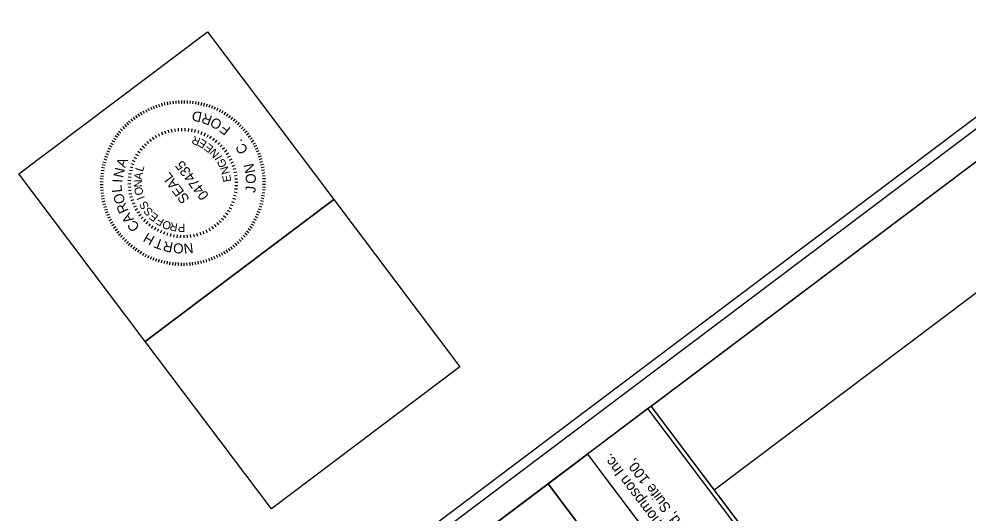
# Model space of a CAD drawing. Extents: x 1262337 to 1264328, y 775525 to 777528.
# Drawn here: x 1262336.8 to 1262789.6, y 776945.7 to 777181.3 of the extents above; entities that cross this region are included whole.
import ezdxf

# ---------------------------------------------------------------- set-up
doc = ezdxf.new("R2010")
doc.units = 0
for name, color, linetype in [('Default', 7, 'Continuous'), ('Raster_Level_0', 7, 'Continuous'), ('Sheet Data Field CELL', 7, 'Continuous'), ('Sheet Layout Plan Border', 7, 'Continuous'), ('Sheet Plan CELL', 7, 'Continuous'), ('Sheet Plan Layout CELL', 7, 'Continuous'), ('Sheet Plot Border Inside CELL', 7, 'Continuous'), ('Sheet Plot Border Outside CELL', 7, 'Continuous')]:
    doc.layers.add(name, color=color, linetype=linetype)

msp = doc.modelspace()

# ---------------------------------------------------------------- linework, layer by layer
at = {"layer": 'Default'}
for p, q in [((1262588.98, 776959.59), (1262607.75, 776973.72)), ((1262607.74, 776973.71), (1262728.05, 776813.98)), ((1262709.29, 776799.84), (1262588.97, 776959.58))]:
    msp.add_line(p, q, dxfattribs=at)
at = {"layer": 'Raster_Level_0'}
for points in [[(1262396.96, 777027.57), (1262336.81, 777107.43), (1262426.65, 777175.09), (1262486.79, 777095.24)], [(1262457.13, 776947.68), (1262396.96, 777027.57), (1262486.79, 777095.24), (1262546.97, 777015.35)], [(1262559.28, 776812.07), (1262499.13, 776891.92), (1262588.97, 776959.59), (1262649.11, 776879.74)]]:
    msp.add_lwpolyline(points, close=True, dxfattribs=at)
at = {"layer": 'Sheet Data Field CELL'}
for p, q in [((1262399.51, 777139.33), (1262400.05, 777138.06)), ((1262400.78, 777139.87), (1262401.28, 777138.57)), ((1262402.08, 777140.31), (1262402.51, 777139.01)), ((1262403.37, 777140.73), (1262403.76, 777139.42)), ((1262404.69, 777141.13), (1262405.05, 777139.78)), ((1262406.04, 777141.42), (1262406.35, 777140.11)), ((1262407.37, 777141.71), (1262407.66, 777140.37)), ((1262408.74, 777141.97), (1262408.93, 777140.61)), ((1262410.1, 777142.15), (1262410.29, 777140.8)), ((1262411.49, 777142.3), (1262411.58, 777140.92)), ((1262412.84, 777142.42), (1262412.92, 777141.03)), ((1262414.21, 777142.43), (1262414.22, 777141.06)), ((1262415.58, 777142.43), (1262415.55, 777141.04)), ((1262416.98, 777142.41), (1262416.89, 777141.02)), ((1262418.33, 777142.29), (1262418.21, 777140.94)), ((1262419.68, 777142.17), (1262419.52, 777140.79)), ((1262421.05, 777141.94), (1262420.86, 777140.6)), ((1262422.42, 777141.71), (1262422.17, 777140.38)), ((1262423.76, 777141.45), (1262423.46, 777140.09)), ((1262425.11, 777141.09), (1262424.75, 777139.75)), ((1262426.43, 777140.71), (1262426.04, 777139.39)), ((1262427.73, 777140.32), (1262427.28, 777139.01)), ((1262429, 777139.83), (1262428.54, 777138.53)), ((1262430.29, 777139.3), (1262429.74, 777138.06)), ((1262392.28, 777135.32), (1262393.08, 777134.18)), ((1262393.44, 777136.08), (1262394.17, 777134.94)), ((1262394.61, 777136.84), (1262395.33, 777135.65)), ((1262395.79, 777137.49), (1262396.45, 777136.31)), ((1262397.02, 777138.18), (1262397.66, 777136.92)), ((1262398.24, 777138.79), (1262398.84, 777137.51)), ((1262431.56, 777138.75), (1262430.96, 777137.47)), ((1262432.77, 777138.17), (1262432.15, 777136.92)), ((1262434, 777137.48), (1262433.33, 777136.31)), ((1262435.18, 777136.81), (1262434.5, 777135.64)), ((1262436.38, 777136.08), (1262435.6, 777134.9)), ((1262437.5, 777135.32), (1262436.69, 777134.16)), ((1262387.04, 777130.89), (1262387.99, 777129.93)), ((1262388.03, 777131.88), (1262388.97, 777130.86)), ((1262389.04, 777132.76), (1262389.93, 777131.75)), ((1262390.09, 777133.67), (1262390.97, 777132.59)), ((1262391.2, 777134.51), (1262392.04, 777133.4)), ((1262438.59, 777134.52), (1262437.79, 777133.43)), ((1262439.7, 777133.67), (1262438.83, 777132.6)), ((1262440.73, 777132.78), (1262439.83, 777131.74)), ((1262441.78, 777131.88), (1262440.81, 777130.85)), ((1262442.76, 777130.87), (1262441.8, 777129.93)), ((1262382.63, 777125.66), (1262383.76, 777124.88)), ((1262383.4, 777126.79), (1262384.52, 777125.95)), ((1262384.28, 777127.86), (1262385.35, 777126.99)), ((1262385.14, 777128.93), (1262386.21, 777127.99)), ((1262386.07, 777129.94), (1262387.11, 777128.97)), ((1262402.57, 777124.6), (1262401.88, 777125.76)), ((1262403.96, 777125.29), (1262403.32, 777126.55)), ((1262405.39, 777125.95), (1262404.82, 777127.25)), ((1262406.84, 777126.49), (1262406.37, 777127.83)), ((1262408.3, 777126.95), (1262407.94, 777128.29)), ((1262409.82, 777127.3), (1262409.55, 777128.72)), ((1262411.34, 777127.61), (1262411.15, 777128.97)), ((1262412.9, 777127.77), (1262412.79, 777129.19)), ((1262414.45, 777127.86), (1262414.44, 777129.22)), ((1262416.02, 777127.84), (1262416.07, 777129.2)), ((1262417.58, 777127.69), (1262417.74, 777129.07)), ((1262419.12, 777127.47), (1262419.35, 777128.84)), ((1262420.66, 777127.19), (1262420.98, 777128.51)), ((1262422.17, 777126.77), (1262422.57, 777128.08)), ((1262423.63, 777126.26), (1262424.09, 777127.56)), ((1262425.05, 777125.64), (1262425.65, 777126.93)), ((1262426.46, 777124.96), (1262427.12, 777126.24)), ((1262443.72, 777129.93), (1262442.7, 777128.98)), ((1262444.63, 777128.87), (1262443.59, 777127.96)), ((1262445.51, 777127.86), (1262444.43, 777126.99)), ((1262446.35, 777126.75), (1262445.24, 777125.91)), ((1262380.43, 777122.13), (1262381.64, 777121.49)), ((1262381.11, 777123.38), (1262382.31, 777122.66)), ((1262381.83, 777124.51), (1262382.98, 777123.76)), ((1262397.59, 777120.85), (1262396.63, 777121.81)), ((1262398.73, 777121.89), (1262397.82, 777122.94)), ((1262399.96, 777122.88), (1262399.13, 777123.98)), ((1262401.21, 777123.76), (1262400.46, 777124.92)), ((1262427.8, 777124.24), (1262428.54, 777125.39)), ((1262429.11, 777123.36), (1262429.93, 777124.52)), ((1262430.35, 777122.44), (1262431.22, 777123.5)), ((1262431.54, 777121.41), (1262432.51, 777122.44)), ((1262432.65, 777120.33), (1262433.68, 777121.29)), ((1262447.19, 777125.64), (1262446.05, 777124.84)), ((1262447.92, 777124.51), (1262446.75, 777123.76)), ((1262448.68, 777123.34), (1262447.49, 777122.62)), ((1262449.35, 777122.12), (1262448.18, 777121.46)), ((1262378.12, 777117.16), (1262379.38, 777116.67)), ((1262378.61, 777118.42), (1262379.89, 777117.9)), ((1262379.2, 777119.72), (1262380.41, 777119.13)), ((1262379.78, 777120.93), (1262381.03, 777120.31)), ((1262393.72, 777115.96), (1262392.53, 777116.67)), ((1262394.59, 777117.27), (1262393.43, 777118.09)), ((1262395.51, 777118.51), (1262394.42, 777119.42)), ((1262396.55, 777119.7), (1262395.47, 777120.64)), ((1262433.72, 777119.15), (1262434.77, 777120.06)), ((1262434.72, 777117.99), (1262435.82, 777118.82)), ((1262435.59, 777116.67), (1262436.72, 777117.46)), ((1262450.02, 777120.93), (1262448.76, 777120.29)), ((1262450.6, 777119.68), (1262449.35, 777119.11)), ((1262451.17, 777118.44), (1262449.9, 777117.9)), ((1262451.68, 777117.14), (1262450.41, 777116.67)), ((1262376.82, 777113.24), (1262378.17, 777112.88)), ((1262377.21, 777114.56), (1262378.52, 777114.17)), ((1262377.63, 777115.89), (1262378.94, 777115.44)), ((1262391.66, 777111.77), (1262390.36, 777112.29)), ((1262392.24, 777113.22), (1262390.98, 777113.78)), ((1262392.95, 777114.59), (1262391.71, 777115.28)), ((1262436.4, 777115.35), (1262437.63, 777116.04)), ((1262437.13, 777113.99), (1262438.42, 777114.59)), ((1262437.79, 777112.56), (1262439.05, 777113.1)), ((1262452.15, 777115.87), (1262450.81, 777115.41)), ((1262452.57, 777114.58), (1262451.22, 777114.16)), ((1262452.93, 777113.23), (1262451.62, 777112.9)), ((1262375.78, 777107.84), (1262377.16, 777107.68)), ((1262375.94, 777109.22), (1262377.35, 777109.02)), ((1262376.2, 777110.55), (1262377.57, 777110.33)), ((1262376.5, 777111.92), (1262377.86, 777111.62)), ((1262390.76, 777108.82), (1262389.4, 777109.11)), ((1262391.14, 777110.3), (1262389.84, 777110.69)), ((1262438.33, 777111.12), (1262439.67, 777111.58)), ((1262438.81, 777109.61), (1262440.13, 777110.01)), ((1262439.17, 777108.09), (1262440.56, 777108.4)), ((1262453.29, 777111.88), (1262451.95, 777111.6)), ((1262453.58, 777110.55), (1262452.21, 777110.29)), ((1262453.81, 777109.21), (1262452.44, 777108.96)), ((1262453.99, 777107.85), (1262452.64, 777107.67)), ((1262375.52, 777103.74), (1262376.87, 777103.68)), ((1262375.54, 777105.14), (1262376.93, 777105.05)), ((1262375.63, 777106.46), (1262377.01, 777106.37)), ((1262390.11, 777104.18), (1262388.72, 777104.21)), ((1262390.22, 777105.71), (1262388.84, 777105.87)), ((1262390.44, 777107.25), (1262389.07, 777107.48)), ((1262439.44, 777106.54), (1262440.81, 777106.8)), ((1262439.64, 777105.01), (1262440.99, 777105.13)), ((1262439.7, 777103.5), (1262441.07, 777103.52)), ((1262454.14, 777106.46), (1262452.79, 777106.34)), ((1262454.26, 777105.11), (1262452.87, 777105.03)), ((1262454.3, 777103.71), (1262452.93, 777103.69)), ((1262375.49, 777102.33), (1262376.89, 777102.38)), ((1262375.53, 777101), (1262376.92, 777101.08)), ((1262375.61, 777099.62), (1262377.03, 777099.74)), ((1262390.1, 777102.61), (1262388.7, 777102.57)), ((1262390.18, 777101.06), (1262388.76, 777100.95)), ((1262390.34, 777099.5), (1262388.98, 777099.31)), ((1262439.34, 777098.79), (1262440.71, 777098.56)), ((1262439.56, 777100.34), (1262440.91, 777100.22)), ((1262439.68, 777101.93), (1262441.07, 777101.84)), ((1262454.16, 777099.58), (1262452.78, 777099.74)), ((1262454.25, 777100.97), (1262452.86, 777101.06)), ((1262454.3, 777102.33), (1262452.91, 777102.36)), ((1262375.77, 777098.23), (1262377.15, 777098.45)), ((1262375.95, 777096.87), (1262377.34, 777097.09)), ((1262376.17, 777095.54), (1262377.58, 777095.82)), ((1262376.49, 777094.17), (1262377.84, 777094.51)), ((1262390.61, 777097.95), (1262389.23, 777097.71)), ((1262390.94, 777096.47), (1262389.63, 777096.08)), ((1262391.42, 777094.97), (1262390.12, 777094.53)), ((1262438.1, 777094.32), (1262439.43, 777093.82)), ((1262438.61, 777095.78), (1262439.92, 777095.39)), ((1262439.03, 777097.29), (1262440.35, 777096.97)), ((1262453.29, 777094.2), (1262451.93, 777094.49)), ((1262453.55, 777095.53), (1262452.22, 777095.78)), ((1262453.81, 777096.86), (1262452.44, 777097.09)), ((1262454, 777098.2), (1262452.63, 777098.43)), ((1262376.82, 777092.85), (1262378.17, 777093.21)), ((1262377.22, 777091.53), (1262378.53, 777091.92)), ((1262377.61, 777090.21), (1262378.94, 777090.67)), ((1262378.08, 777088.94), (1262379.38, 777089.44)), ((1262391.96, 777093.52), (1262390.7, 777092.98)), ((1262392.62, 777092.09), (1262391.4, 777091.48)), ((1262393.35, 777090.73), (1262392.15, 777090.01)), ((1262436.04, 777090.12), (1262437.23, 777089.41)), ((1262436.83, 777091.45), (1262438.08, 777090.83)), ((1262437.51, 777092.86), (1262438.77, 777092.3)), ((1262452.16, 777090.22), (1262450.85, 777090.67)), ((1262452.58, 777091.49), (1262451.23, 777091.91)), ((1262452.94, 777092.83), (1262451.59, 777093.2)), ((1262378.62, 777087.67), (1262379.89, 777088.21)), ((1262379.16, 777086.4), (1262380.44, 777087)), ((1262379.77, 777085.18), (1262380.99, 777085.79)), ((1262394.19, 777089.37), (1262393.03, 777088.62)), ((1262395.07, 777088.12), (1262393.97, 777087.29)), ((1262396.06, 777086.89), (1262394.98, 777086.02)), ((1262397.1, 777085.75), (1262396.1, 777084.76)), ((1262432.2, 777085.26), (1262433.16, 777084.23)), ((1262433.27, 777086.37), (1262434.28, 777085.44)), ((1262434.31, 777087.56), (1262435.37, 777086.69)), ((1262435.2, 777088.84), (1262436.36, 777088.03)), ((1262449.97, 777085.15), (1262448.76, 777085.8)), ((1262450.59, 777086.39), (1262449.34, 777086.95)), ((1262451.14, 777087.66), (1262449.9, 777088.21)), ((1262451.7, 777088.91), (1262450.37, 777089.41)), ((1262380.43, 777083.92), (1262381.64, 777084.61)), ((1262381.11, 777082.77), (1262382.3, 777083.49)), ((1262381.84, 777081.57), (1262383.01, 777082.33)), ((1262382.6, 777080.48), (1262383.74, 777081.28)), ((1262398.21, 777084.68), (1262397.31, 777083.63)), ((1262399.4, 777083.64), (1262398.53, 777082.58)), ((1262400.64, 777082.72), (1262399.87, 777081.59)), ((1262401.95, 777081.85), (1262401.21, 777080.7)), ((1262403.32, 777081.08), (1262402.67, 777079.87)), ((1262404.73, 777080.4), (1262404.14, 777079.18)), ((1262425.86, 777080.78), (1262426.43, 777079.53)), ((1262427.22, 777081.51), (1262427.91, 777080.28)), ((1262428.54, 777082.32), (1262429.29, 777081.16)), ((1262429.83, 777083.23), (1262430.66, 777082.13)), ((1262431.02, 777084.19), (1262431.93, 777083.14)), ((1262447.16, 777080.45), (1262446.03, 777081.23)), ((1262447.92, 777081.57), (1262446.77, 777082.32)), ((1262448.68, 777082.73), (1262447.48, 777083.46)), ((1262449.35, 777083.91), (1262448.15, 777084.62)), ((1262383.4, 777079.33), (1262384.51, 777080.17)), ((1262384.28, 777078.25), (1262385.36, 777079.13)), ((1262385.12, 777077.21), (1262386.17, 777078.13)), ((1262386.07, 777076.19), (1262387.09, 777077.13)), ((1262387.02, 777075.17), (1262388.02, 777076.15)), ((1262406.19, 777079.81), (1262405.66, 777078.52)), ((1262407.62, 777079.34), (1262407.2, 777078.01)), ((1262409.13, 777078.92), (1262408.81, 777077.54)), ((1262410.66, 777078.57), (1262410.4, 777077.24)), ((1262412.21, 777078.35), (1262412.05, 777076.97)), ((1262413.77, 777078.27), (1262413.68, 777076.88)), ((1262415.31, 777078.23), (1262415.32, 777076.86)), ((1262416.86, 777078.32), (1262417, 777076.92)), ((1262418.41, 777078.47), (1262418.6, 777077.11)), ((1262419.96, 777078.74), (1262420.24, 777077.39)), ((1262421.45, 777079.14), (1262421.81, 777077.8)), ((1262422.96, 777079.62), (1262423.42, 777078.28)), ((1262424.43, 777080.12), (1262424.97, 777078.86)), ((1262442.74, 777075.15), (1262441.77, 777076.15)), ((1262443.72, 777076.18), (1262442.71, 777077.1)), ((1262444.65, 777077.18), (1262443.58, 777078.12)), ((1262445.51, 777078.25), (1262444.44, 777079.12)), ((1262446.39, 777079.32), (1262445.27, 777080.17)), ((1262388.02, 777074.23), (1262388.94, 777075.24)), ((1262389.02, 777073.3), (1262389.96, 777074.37)), ((1262390.09, 777072.44), (1262390.96, 777073.51)), ((1262391.16, 777071.56), (1262392.01, 777072.68)), ((1262392.25, 777070.76), (1262393.07, 777071.92)), ((1262437.48, 777070.76), (1262436.68, 777071.9)), ((1262438.62, 777071.56), (1262437.78, 777072.67)), ((1262439.66, 777072.41), (1262438.79, 777073.49)), ((1262440.74, 777073.28), (1262439.83, 777074.32)), ((1262441.77, 777074.23), (1262440.82, 777075.25)), ((1262393.41, 777070.03), (1262394.16, 777071.18)), ((1262394.57, 777069.27), (1262395.3, 777070.47)), ((1262395.78, 777068.56), (1262396.46, 777069.8)), ((1262396.98, 777067.91), (1262397.64, 777069.19)), ((1262398.19, 777067.33), (1262398.82, 777068.57)), ((1262399.46, 777066.78), (1262400.05, 777068.05)), ((1262400.75, 777066.25), (1262401.28, 777067.54)), ((1262402.06, 777065.79), (1262402.51, 777067.1)), ((1262427.71, 777065.8), (1262427.28, 777067.1)), ((1262429.01, 777066.24), (1262428.51, 777067.54)), ((1262430.28, 777066.78), (1262429.74, 777068.05)), ((1262431.55, 777067.32), (1262430.95, 777068.6)), ((1262432.77, 777067.93), (1262432.16, 777069.15)), ((1262433.99, 777068.56), (1262433.3, 777069.77)), ((1262435.18, 777069.27), (1262434.46, 777070.46)), ((1262436.34, 777069.97), (1262435.59, 777071.13)), ((1262403.35, 777065.34), (1262403.78, 777066.68)), ((1262404.71, 777064.98), (1262405.03, 777066.3)), ((1262406.04, 777064.66), (1262406.33, 777066.02)), ((1262407.36, 777064.33), (1262407.62, 777065.73)), ((1262408.73, 777064.1), (1262408.93, 777065.51)), ((1262410.07, 777063.92), (1262410.27, 777065.32)), ((1262411.42, 777063.79), (1262411.58, 777065.17)), ((1262412.81, 777063.7), (1262412.9, 777065.09)), ((1262414.18, 777063.64), (1262414.2, 777065.04)), ((1262415.58, 777063.62), (1262415.53, 777065.03)), ((1262416.95, 777063.69), (1262416.87, 777065.08)), ((1262418.33, 777063.77), (1262418.18, 777065.16)), ((1262419.65, 777063.94), (1262419.51, 777065.31)), ((1262421.05, 777064.14), (1262420.83, 777065.48)), ((1262422.39, 777064.37), (1262422.13, 777065.74)), ((1262423.75, 777064.62), (1262423.44, 777066)), ((1262425.1, 777064.98), (1262424.74, 777066.33)), ((1262426.38, 777065.35), (1262425.99, 777066.66))]:
    msp.add_line(p, q, dxfattribs=at)
msp.add_lwpolyline([(1262756.89, 776835.69), (1262636.54, 776995.47), (1262607.71, 776973.75), (1262728.05, 776813.98)], close=True, dxfattribs=at)
at = {"layer": 'Sheet Layout Plan Border'}
msp.add_lwpolyline([(1264180.22, 776342.84), (1263337.92, 777461.13), (1262668.14, 776956.65), (1262782.01, 776805.47), (1262613.08, 776678.23), (1263341.52, 775711.12)], close=True, dxfattribs=at)
at = {"layer": 'Sheet Plan CELL'}
msp.add_lwpolyline([(1262469.12, 776869.36), (1263371.6, 775671.18), (1264210.31, 776302.91), (1263307.84, 777501.07)], close=True, dxfattribs=at)
at = {"layer": 'Sheet Plan Layout CELL'}
for points in [[(1263371.64, 775671.18), (1264210.31, 776302.91), (1263307.85, 777501.06), (1262638.07, 776996.57), (1262782.01, 776805.47), (1262613.08, 776678.23)], [(1262782.01, 776805.47), (1262638.06, 776996.59), (1262469.11, 776869.37), (1262613.08, 776678.23)]]:
    msp.add_lwpolyline(points, close=True, dxfattribs=at)
at = {"layer": 'Sheet Plot Border Inside CELL'}
msp.add_lwpolyline([(1264304.66, 776181.82), (1263302.32, 777512.55), (1262459.63, 776877.83), (1263461.96, 775547.09)], close=True, dxfattribs=at)
at = {"layer": 'Sheet Plot Border Outside CELL'}
msp.add_lwpolyline([(1264328.45, 776183.46), (1263315.59, 777528.19), (1262440.94, 776869.39), (1263453.8, 775524.67)], close=True, dxfattribs=at)

# ---------------------------------------------------------------- texts
at = {"layer": 'Sheet Data Field CELL'}
for s, height, rotation, p in [('D', 4.79, 167.4842, (1262424.36, 777136.64)), ('R', 4.79, 158.8526, (1262429.29, 777134.84)), ('O', 4.79, 149.9332, (1262434.05, 777132.23)), ('F', 4.79, 141.7332, (1262438.01, 777129.2)), ('R', 3.88, 156.6864, (1262423.62, 777124.2)), ('E', 3.88, 148.3844, (1262426.68, 777122.54)), ('E', 3.88, 140.0823, (1262429.82, 777120.05)), ('C', 4.79, 119.5067, (1262446.18, 777118.51)), ('.', 4.79, 128.1383, (1262443.51, 777123.03)), ('N', 3.88, 131.7803, (1262432.58, 777117.09)), ('A', 4.79, 68.9785, (1262387.35, 777110.08)), ('047435', 4.791, 126.9874, (1262427.55, 777097.19)), ('I', 3.88, 123.4782, (1262433.84, 777115.58)), ('G', 3.88, 115.1762, (1262436.07, 777111.5)), ('N', 4.79, 101.7398, (1262449.41, 777108.22)), ('N', 4.79, 78.0086, (1262386.4, 777105.29)), ('A', 3.88, 82.4627, (1262395.42, 777104.46)), ('L', 3.88, 72.7539, (1262395.81, 777108.23)), ('SEAL', 4.791, 126.9874, (1262418.34, 777095.5)), ('N', 3.88, 106.8742, (1262437.33, 777107.84)), ('I', 4.79, 87.0386, (1262385.96, 777103.15)), ('N', 3.88, 92.1716, (1262395.52, 777101.06)), ('E', 3.88, 98.5721, (1262437.96, 777103.81)), ('O', 4.79, 92.8205, (1262449.79, 777102.81)), ('L', 4.79, 96.0686, (1262385.99, 777098.74)), ('O', 3.88, 101.8804, (1262396.2, 777097.61)), ('J', 4.79, 85.3397, (1262449.46, 777098.27)), ('O', 4.79, 105.0986, (1262387.52, 777093.77)), ('I', 3.88, 111.5892, (1262396.82, 777095.92)), ('S', 3.88, 121.298, (1262398.96, 777091.89)), ('R', 4.79, 114.1287, (1262389.2, 777089.88)), ('S', 3.88, 131.0069, (1262401.03, 777089.38)), ('A', 4.79, 123.1587, (1262391.76, 777085.75)), ('C', 4.79, 132.1887, (1262394.65, 777082.4)), ('E', 3.88, 140.7157, (1262403.54, 777087.24)), ('F', 3.88, 150.4245, (1262406.35, 777085.58)), ('O', 3.88, 160.1334, (1262409.76, 777084.07)), ('R', 3.88, 169.8422, (1262412.69, 777083.69)), ('P', 3.88, 179.551, (1262415.99, 777083.6)), ('H', 4.79, 150.2488, (1262401.92, 777077.27)), ('T', 4.79, 159.2788, (1262406.1, 777075.56)), ('R', 4.79, 168.3088, (1262410.54, 777074.52)), ('O', 4.79, 177.3388, (1262415.37, 777074.15)), ('N', 4.79, 186.3689, (1262419.61, 777074.58)), ('Johnson, Mirmiran, & Thompson Inc.', 5.1108, 126.9874, (1262685.88, 776885.34)), ('4700 Falls of Neuse Rd, Suite 100, ', 4.9648, 126.9874, (1262691.87, 776889.85))]:
    msp.add_text(s, height=height, rotation=rotation, dxfattribs=at).set_placement(p)

doc.saveas('drawing.dxf')
